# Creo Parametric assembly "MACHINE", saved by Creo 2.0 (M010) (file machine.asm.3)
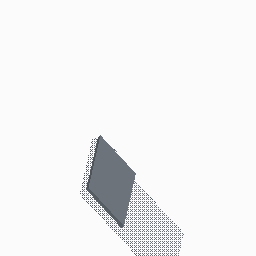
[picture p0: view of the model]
Units: Inch lbm Second (Pro/E Default); INCH, POUND, SECS

Created from: INLBS_ASM_DESIGN.ASM

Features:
  1. datum plane "ASM_RIGHT"
  2. datum plane "ASM_TOP"
  3. datum plane "ASM_FRONT"
  4. coordinate system
  5. component "YMOTOR"
  6. coordinate system
  7. component "BASE_BOARD"
  8. component "TOPBOARD"

Other named items: ACS0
